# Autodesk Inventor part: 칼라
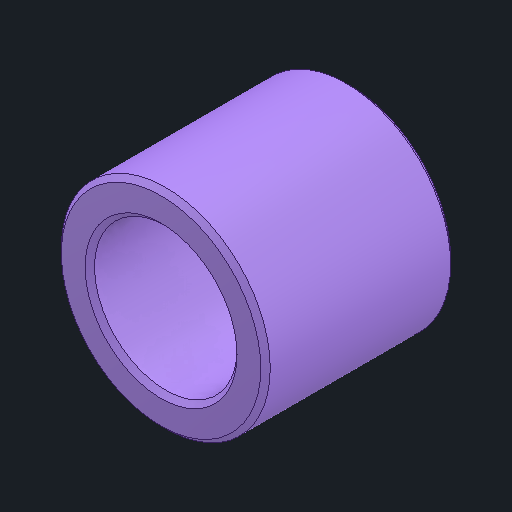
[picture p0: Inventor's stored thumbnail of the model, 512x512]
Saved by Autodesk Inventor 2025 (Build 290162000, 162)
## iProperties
Created: 2025-08
Part Number: 칼라
Material: 스테인리스강
Document SubType Name: Modeling
Designer: infra027
Density: 8.08 g/cm^3
Appearance: 기본값
Author: jhkim
Sending System: Autodesk Inventor 2026
Preprocessor: ST-DEVELOPER v20.1
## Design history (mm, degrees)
feature "솔리드1"
node "솔리드2"
